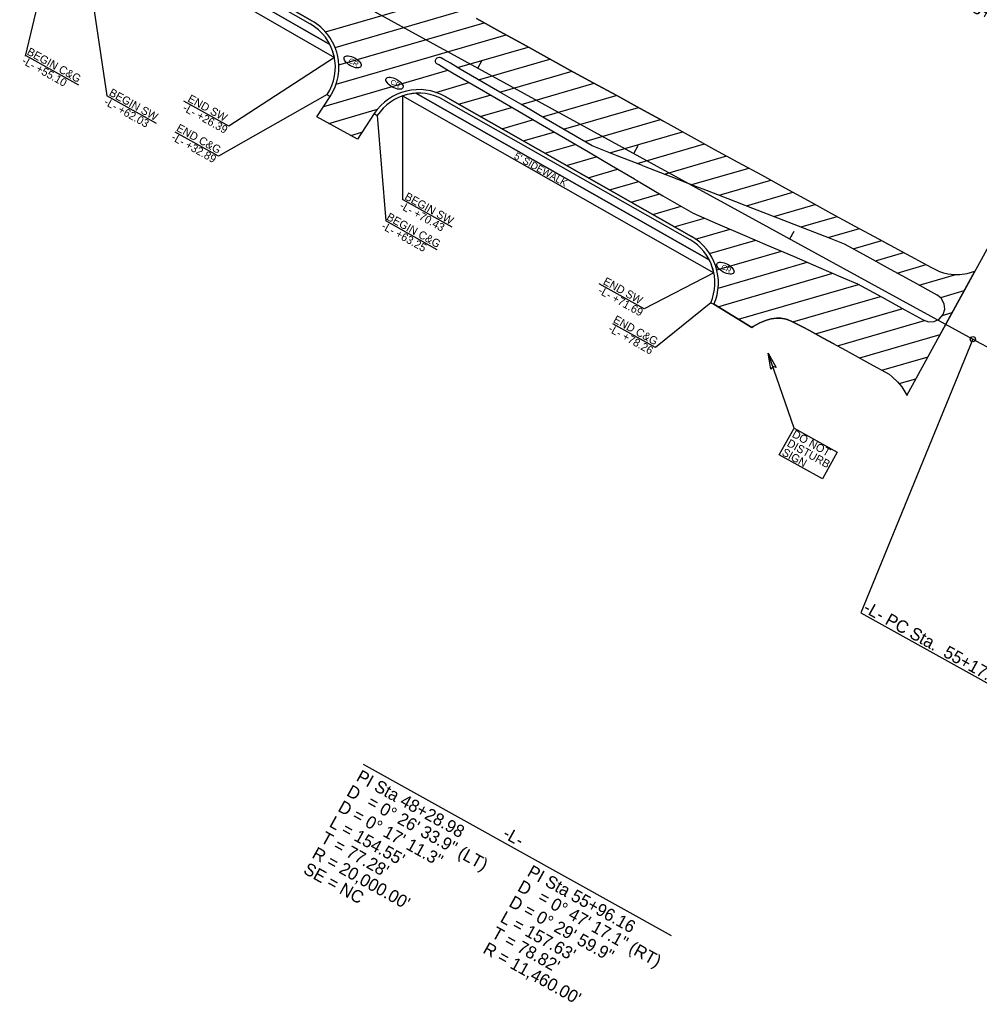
# Model space of a CAD drawing. Extents: x 1762196 to 1766326, y 709922 to 713142.
# Drawn here: x 1765252 to 1765792, y 709922 to 710474 of the extents above; entities that cross this region are included whole.
import ezdxf

# ---------------------------------------------------------------- set-up
doc = ezdxf.new("R2010")
doc.units = 0
for name, color, linetype in [('Old_Level_40', 7, 'Continuous'), ('Pattern 1', 7, 'Continuous'), ('Pattern 2', 7, 'Continuous'), ('Pattern 5', 7, 'Continuous'), ('Prop Conc 2ft 6in Curb and Gutter', 7, 'Continuous'), ('Prop Dimension', 7, 'Continuous'), ('Prop EOT', 7, 'Continuous'), ('Prop Horizontal Alignment', 7, 'Continuous'), ('Prop Horizontal Alignment Curve and Spiral Data', 7, 'Continuous'), ('Prop Horizontal Alignment Station Label', 7, 'Continuous'), ('Prop Horizontal Alignment Tick Large', 7, 'Continuous'), ('Prop Horizontal Alignment Tick Small', 7, 'Continuous'), ('Prop Terminator CELL', 7, 'Continuous')]:
    doc.layers.add(name, color=color, linetype=linetype)

msp = doc.modelspace()

# ---------------------------------------------------------------- linework, layer by layer
at = {"layer": 'Old_Level_40'}
for p, q in [((1765416.65, 710473.61), (1765368.58, 710501.28)), ((1765424.25, 710467.47), (1765488.61, 710486.17)), ((1765429.7, 710458.64), (1765501.05, 710479.37)), ((1765431.8, 710448.84), (1765513.45, 710472.56)), ((1765430.27, 710437.98), (1765525.81, 710465.73)), ((1765498.56, 710447.4), (1765538.19, 710458.92)), ((1765510.39, 710440.43), (1765550.48, 710452.07)), ((1765423.27, 710425.53), (1765493.1, 710445.82)), ((1765522.37, 710433.49), (1765562.97, 710445.29)), ((1765486.24, 710433.41), (1765505.02, 710438.87)), ((1765534.31, 710426.55), (1765575.41, 710438.49)), ((1765419.41, 710419.67), (1765426.89, 710431.03)), ((1765630.05, 710352.35), (1765491.58, 710431.03)), ((1765499.13, 710426.74), (1765516.9, 710431.9)), ((1765546.22, 710419.59), (1765587.81, 710431.68)), ((1765426.18, 710415.96), (1765453.51, 710423.9)), ((1765511.26, 710419.85), (1765528.83, 710424.96)), ((1765558.15, 710412.65), (1765600.28, 710424.89)), ((1765442.29, 710407.14), (1765419.41, 710419.67)), ((1765451.7, 710421.44), (1765442.29, 710407.14)), ((1765523.38, 710412.96), (1765540.76, 710418.01)), ((1765570.08, 710405.7), (1765612.64, 710418.06)), ((1765438.6, 710409.16), (1765444.8, 710410.96)), ((1765535.51, 710406.07), (1765552.67, 710411.06)), ((1765584.21, 710399.39), (1765625.03, 710411.25)), ((1765547.63, 710399.18), (1765564.58, 710404.1)), ((1765599.58, 710393.44), (1765637.41, 710404.43)), ((1765559.76, 710392.29), (1765576.51, 710397.16)), ((1765614.9, 710387.48), (1765649.86, 710397.64)), ((1765571.89, 710385.4), (1765588.44, 710390.21)), ((1765630.28, 710381.53), (1765662.32, 710390.84)), ((1765584.01, 710378.51), (1765600.38, 710383.26)), ((1765645.59, 710375.57), (1765674.68, 710384.02)), ((1765596.14, 710371.62), (1765612.3, 710376.31)), ((1765660.93, 710369.61), (1765687.11, 710377.22)), ((1765608.26, 710364.73), (1765624.22, 710369.36)), ((1765676.32, 710363.67), (1765699.64, 710370.44)), ((1765620.39, 710357.83), (1765637.31, 710362.75)), ((1765691.66, 710357.71), (1765712.03, 710363.63)), ((1765691.66, 710357.71), (1765712.03, 710363.63)), ((1765707, 710351.75), (1765724.53, 710356.85)), ((1765707, 710351.75), (1765724.53, 710356.85)), ((1765632.36, 710350.9), (1765651.74, 710356.53)), ((1765640.27, 710342.78), (1765666.21, 710350.32)), ((1765721.05, 710345.42), (1765737.02, 710350.06)), ((1765721.05, 710345.42), (1765737.02, 710350.06)), ((1765644.32, 710333.55), (1765680.66, 710344.1)), ((1765733.46, 710338.61), (1765749.51, 710343.28)), ((1765733.46, 710338.61), (1765749.51, 710343.28)), ((1765645.07, 710323.35), (1765695.11, 710337.89)), ((1765645.07, 710323.35), (1765695.11, 710337.89)), ((1765745.78, 710331.83), (1765762.03, 710336.55)), ((1765644.94, 710312.9), (1765709.55, 710331.67)), ((1765644.94, 710312.9), (1765709.55, 710331.67)), ((1765758.16, 710325.01), (1765778.66, 710330.96)), ((1765656.47, 710305.83), (1765723.91, 710325.43)), ((1765656.47, 710305.83), (1765723.91, 710325.43)), ((1765687.14, 710304.33), (1765736.43, 710318.65)), ((1765687.14, 710304.33), (1765736.43, 710318.65)), ((1765770.31, 710318.12), (1765783.43, 710321.94)), ((1765664.01, 710301.21), (1765642.7, 710314.27)), ((1765699.71, 710297.61), (1765747.05, 710311.37)), ((1765699.84, 710297.61), (1765748.82, 710311.84)), ((1765699.84, 710297.61), (1765748.82, 710311.84)), ((1765770.99, 710307.91), (1765776.65, 710309.55)), ((1765712.2, 710290.83), (1765761.14, 710305.05)), ((1765724.79, 710284.07), (1765769.86, 710297.17)), ((1765737.02, 710277.21), (1765763.08, 710284.78)), ((1765746.79, 710269.64), (1765756.3, 710272.4))]:
    msp.add_line(p, q, dxfattribs=at)
for points in [[(1765509.19, 710474.92), (1765522.3, 710467.65), (1765535.46, 710460.45), (1765548.54, 710453.13), (1765561.72, 710445.97), (1765574.88, 710438.78), (1765588.03, 710431.56), (1765601.2, 710424.38), (1765614.33, 710417.13)], [(1765614.33, 710417.13), (1765616.73, 710415.82), (1765629.87, 710408.59), (1765643, 710401.35), (1765656.19, 710394.21), (1765669.35, 710386.97), (1765682.47, 710379.7), (1765695.7, 710372.63), (1765708.82, 710365.37), (1765722, 710358.23), (1765735.18, 710351.06), (1765740.73, 710348.05)], [(1765710.03, 710292.01), (1765704.05, 710295.25), (1765696.38, 710299.53), (1765692.83, 710301.37), (1765685.83, 710305.02), (1765683.33, 710305.94), (1765680.35, 710306.48), (1765677.96, 710306.5), (1765674.95, 710306.08), (1765672.26, 710305.31), (1765668.48, 710303.83), (1765664.77, 710301.74), (1765664.01, 710301.21)]]:
    msp.add_lwpolyline(points, dxfattribs=at)
for centre, start, end in [((1765401.83, 710447.53), 326.6444, 60.3918), ((1765476.76, 710404.95), 60.3918, 146.6444), ((1765615.21, 710326.29), 336.3971, 60.3494)]:
    msp.add_arc(centre, 30, start, end, dxfattribs=at)
at = {"layer": 'Pattern 1'}
for p, q in [((1765362.98, 710491.24), (1765429.28, 710453.08)), ((1765467.63, 710431.42), (1765642.63, 710331.97)), ((1765640.07, 710339.18), (1765475.14, 710432.9))]:
    msp.add_line(p, q, dxfattribs=at)
msp.add_lwpolyline([(1765426.75, 710460.3), (1765365.41, 710495.6), (1765365.38, 710495.63)], dxfattribs=at)
for centre, start, end in [((1765401.83, 710447.53), 11.4296, 27.1395), ((1765476.76, 710404.95), 93.327, 109.0374), ((1765615.21, 710326.29), 11.7149, 27.4135)]:
    msp.add_arc(centre, 28, start, end, dxfattribs=at)
at = {"layer": 'Pattern 2'}
for p, q in [((1765365.34, 710495.65), (1765426.75, 710460.3)), ((1765362.85, 710491.31), (1765429.28, 710453.08)), ((1765467.63, 710431.42), (1765642.63, 710331.97)), ((1765475.14, 710432.9), (1765640.07, 710339.18))]:
    msp.add_line(p, q, dxfattribs=at)
for centre, start, end in [((1765401.83, 710447.53), 11.4296, 27.1395), ((1765476.76, 710404.95), 93.327, 109.0374), ((1765615.21, 710326.29), 11.7149, 27.4135)]:
    msp.add_arc(centre, 28, start, end, dxfattribs=at)
at = {"layer": 'Pattern 5'}
for centre in [(1765439.54, 710450.57), (1765463.08, 710438.57), (1765649.13, 710334.56)]:
    msp.add_ellipse(centre, major_axis=(4.7, -2.63), ratio=0.462467, dxfattribs=at)
at = {"layer": 'Prop Conc 2ft 6in Curb and Gutter'}
for p, q in [((1765367.58, 710499.55), (1765415.65, 710471.88)), ((1765425.22, 710432.13), (1765426.89, 710431.03)), ((1765490.6, 710429.29), (1765629.06, 710350.61)), ((1765451.7, 710421.44), (1765453.37, 710420.34)), ((1765640.87, 710315.08), (1765642.7, 710314.27))]:
    msp.add_line(p, q, dxfattribs=at)
for centre, start, end in [((1765401.83, 710447.53), 326.6444, 60.3918), ((1765476.76, 710404.95), 60.3918, 146.6444), ((1765615.21, 710326.29), 336.3971, 60.3494)]:
    msp.add_arc(centre, 28, start, end, dxfattribs=at)
at = {"layer": 'Prop Dimension'}
for p, q in [((1765286.09, 710533.81), (1765301.32, 710431.55)), ((1765271.97, 710522.45), (1765255.34, 710453.77)), ((1765285.5, 710437.52), (1765255.98, 710453.96)), ((1765429.28, 710453.08), (1765369.91, 710414.35)), ((1765329.31, 710415.98), (1765301.32, 710431.55)), ((1765425.22, 710432.13), (1765364.05, 710397.58)), ((1765467.63, 710431.42), (1765467.51, 710373.14)), ((1765369.91, 710414.35), (1765344.58, 710428.44)), ((1765453.37, 710420.34), (1765458.14, 710361.09)), ((1765364.05, 710397.58), (1765339.77, 710411.1)), ((1765495.5, 710357.58), (1765467.51, 710373.14)), ((1765487.13, 710344.95), (1765458.14, 710361.09)), ((1765642.63, 710331.97), (1765603.48, 710311.64)), ((1765603.48, 710311.64), (1765578.15, 710325.72)), ((1765640.87, 710315.08), (1765609.75, 710289.92)), ((1765609.75, 710289.92), (1765585.8, 710303.26)), ((1765687.74, 710244.49), (1765673.21, 710286.72))]:
    msp.add_line(p, q, dxfattribs=at)
msp.add_lwpolyline([(1765687.74, 710244.49), (1765711.96, 710231), (1765703.65, 710216.07), (1765679.43, 710229.56)], close=True, dxfattribs=at)
at = {"layer": 'Prop EOT'}
for p, q in [((1765368.58, 710501.28), (1765416.65, 710473.61)), ((1765419.41, 710419.67), (1765426.89, 710431.03)), ((1765491.58, 710431.03), (1765630.05, 710352.35)), ((1765442.29, 710407.14), (1765419.41, 710419.67)), ((1765451.7, 710421.44), (1765442.29, 710407.14)), ((1765751.1, 710262.91), (1765789.38, 710332.79)), ((1765642.7, 710314.27), (1765643.62, 710313.87)), ((1765642.7, 710314.27), (1765664.01, 710301.21))]:
    msp.add_line(p, q, dxfattribs=at)
for points in [[(1765614.33, 710417.13), (1765601.2, 710424.38), (1765588.03, 710431.56), (1765574.88, 710438.78), (1765561.72, 710445.97), (1765548.54, 710453.13), (1765535.46, 710460.45), (1765522.3, 710467.65), (1765509.19, 710474.92)], [(1765598.03, 710384.61), (1765585.08, 710392.17), (1765572.11, 710399.72), (1765559.15, 710407.27), (1765546.22, 710414.83), (1765533.26, 710422.38), (1765520.29, 710429.91), (1765507.36, 710437.5), (1765497.97, 710442.98), (1765492.52, 710446.16), (1765488.03, 710448.8), (1765486.91, 710449.47), (1765486.37, 710450.09), (1765486.15, 710450.79), (1765486.13, 710451.51), (1765486.46, 710452.27), (1765487.02, 710452.8), (1765487.68, 710453.08), (1765488.36, 710453.13), (1765488.98, 710452.95)], [(1765602.48, 710392.32), (1765588.31, 710397.79), (1765574.18, 710403.31), (1765561.22, 710410.86), (1765548.31, 710418.37), (1765535.36, 710425.94), (1765522.38, 710433.45), (1765509.42, 710440.99), (1765502.29, 710445.19), (1765500.06, 710446.5), (1765494.64, 710449.74), (1765490.9, 710451.84), (1765488.98, 710452.95)], [(1765614.33, 710417.13), (1765616.73, 710415.82), (1765629.87, 710408.59), (1765643, 710401.35), (1765656.19, 710394.21), (1765669.35, 710386.97), (1765682.47, 710379.7), (1765695.7, 710372.63), (1765708.82, 710365.37), (1765722, 710358.23), (1765735.18, 710351.06), (1765748.36, 710343.9), (1765765.08, 710334.91), (1765769.48, 710332.76), (1765771.8, 710331.93), (1765774.13, 710331.39), (1765777.98, 710330.96), (1765781.01, 710330.96), (1765785, 710331.51), (1765789.38, 710332.79)], [(1765602.48, 710392.32), (1765604.38, 710391.54), (1765618.38, 710386.13), (1765632.37, 710380.73), (1765636.44, 710379.13), (1765650.42, 710373.68), (1765664.45, 710368.25), (1765678.45, 710362.85), (1765693.5, 710356.99)], [(1765598.03, 710384.61), (1765600.94, 710382.94), (1765614.03, 710375.3), (1765627.13, 710367.66), (1765630.98, 710365.49), (1765644.75, 710359.53), (1765658.81, 710353.5), (1765672.61, 710347.58), (1765687.73, 710341.05)], [(1765693.5, 710356.99), (1765707.49, 710351.56), (1765715.88, 710348.25), (1765728.62, 710341.28), (1765741.76, 710334.04), (1765754.89, 710326.81), (1765768.03, 710319.56)], [(1765687.73, 710341.05), (1765701.52, 710335.14), (1765715.29, 710329.19), (1765723.33, 710325.74), (1765736.89, 710318.4), (1765750.03, 710311.17), (1765760.27, 710305.52), (1765763.43, 710304.45), (1765766.59, 710304.62), (1765769.32, 710305.95), (1765771.57, 710308.59), (1765772.5, 710311.5), (1765772.24, 710314.5), (1765770.55, 710317.67), (1765768.03, 710319.56)], [(1765664.01, 710301.21), (1765664.77, 710301.74), (1765668.48, 710303.83), (1765672.26, 710305.31), (1765674.95, 710306.08), (1765677.96, 710306.5), (1765680.35, 710306.48), (1765683.33, 710305.94), (1765685.83, 710305.02), (1765692.83, 710301.37), (1765696.38, 710299.53), (1765704.05, 710295.25), (1765717.03, 710288.21), (1765730.21, 710281.03), (1765741.17, 710274.88), (1765742.95, 710273.54), (1765745.94, 710270.68), (1765748.33, 710267.76), (1765751.18, 710263.06)]]:
    msp.add_lwpolyline(points, dxfattribs=at)
for centre, start, end in [((1765401.83, 710447.53), 326.6444, 60.3918), ((1765476.76, 710404.95), 60.3918, 146.6444), ((1765615.21, 710326.29), 336.3971, 60.3494)]:
    msp.add_arc(centre, 30, start, end, dxfattribs=at)
at = {"layer": 'Prop Horizontal Alignment'}
msp.add_line((1765252.32, 710588.23), (1765788.26, 710294.65), dxfattribs=at)
msp.add_arc((1760282.51, 700243.86), 11460, 60.49827, 61.286353, dxfattribs=at)
at = {"layer": 'Prop Horizontal Alignment Curve and Spiral Data'}
msp.add_line((1765445.49, 710055.65), (1765618.61, 709959.24), dxfattribs=at)
at = {"layer": 'Prop Horizontal Alignment Station Label'}
for p, q in [((1765859.08, 710460.02), (1765773.05, 710302.98)), ((1765788.26, 710294.65), (1765725.38, 710140.71)), ((1765725.38, 710140.71), (1765816.18, 710090.15))]:
    msp.add_line(p, q, dxfattribs=at)
msp.add_circle((1765788.26, 710294.65), 1.5, dxfattribs=at)
at = {"layer": 'Prop Horizontal Alignment Tick Large'}
for q in [(1765776.89, 710310), (1765776.89, 710310), (1765769.2, 710295.96), (1765769.2, 710295.96)]:
    msp.add_line((1765773.05, 710302.98), q, dxfattribs=at)
at = {"layer": 'Prop Horizontal Alignment Tick Small'}
for p, q in [((1765509.94, 710447.11), (1765512.34, 710451.49)), ((1765509.94, 710447.11), (1765512.34, 710451.49)), ((1765597.64, 710399.07), (1765600.04, 710403.45)), ((1765597.64, 710399.07), (1765600.04, 710403.45)), ((1765685.34, 710351.02), (1765687.75, 710355.41)), ((1765685.35, 710351.02), (1765687.75, 710355.41))]:
    msp.add_line(p, q, dxfattribs=at)
at = {"layer": 'Prop Terminator CELL'}
msp.add_lwpolyline([(1765674.67, 710277.7), (1765673.21, 710286.72), (1765677.67, 710278.68), (1765675.78, 710279.25)], close=True, dxfattribs=at)

# ---------------------------------------------------------------- texts
at = {"layer": 'Pattern 5'}
for p in [(1765436.88, 710450.43), (1765460.41, 710438.44), (1765646.47, 710334.43)]:
    msp.add_text('CR', height=2.88, rotation=330.7692, dxfattribs=at).set_placement(p)
at = {"layer": 'Prop Dimension'}
for s, height, rotation, p in [('BEGIN C&G', 4.5, 330.8875, (1765255.99, 710454.95)), ('-L- +55.10', 4.5, 330.8875, (1765253.15, 710449.84)), ('BEGIN SW', 4.5, 330.9251, (1765302.16, 710431.92)), ('-L- +62.03', 4.5, 330.9251, (1765299.32, 710426.8)), ('END SW', 4.5, 330.9251, (1765346.4, 710428.51)), ('-L- +26.39', 4.5, 330.9251, (1765343.55, 710423.4)), ('END C&G', 4.5, 330.8875, (1765340.01, 710412.03)), ('-L- +32.89', 4.5, 330.8875, (1765337.16, 710406.91)), ("5' SIDEWALK", 4, 330.8354, (1765529.92, 710396.46)), ('BEGIN SW', 4.5, 330.9251, (1765468.35, 710373.51)), ('-L- +70.43', 4.5, 330.9251, (1765465.51, 710368.4)), ('BEGIN C&G', 4.5, 330.8875, (1765458.16, 710362.04)), ('-L- +63.25', 4.5, 330.8875, (1765455.32, 710356.93)), ('END SW', 4.5, 330.9251, (1765579.97, 710325.8)), ('-L- +71.69', 4.5, 330.9251, (1765577.13, 710320.68)), ('END C&G', 4.5, 330.8875, (1765585.67, 710304.35)), ('-L- +78.26', 4.5, 330.8875, (1765582.82, 710299.24)), ('DO NOT ', 4.5, 330.8875, (1765686.2, 710239.89)), ('DISTURB', 4.5, 330.8875, (1765683.35, 710234.78)), ('SIGN', 4.5, 330.8875, (1765680.51, 710229.67))]:
    msp.add_text(s, height=height, rotation=rotation, dxfattribs=at).set_placement(p)
at = {"layer": 'Prop Horizontal Alignment Curve and Spiral Data'}
for s, p in [('PI Sta 48+28.98', (1765441.04, 710046.68)), ('D', (1765435.59, 710038.27)), ('= 0%%d 26\' 33.9" (LT)', (1765446.96, 710032.28)), ('D = 0%%d 17\' 11.3"', (1765430.72, 710029.53)), ("L = 154.55'", (1765425.86, 710020.8)), ("T = 77.28'", (1765420.99, 710012.06)), ('-L-', (1765523.39, 710014.67)), ("R = 20,000.00'", (1765416.13, 710003.32)), ('SE = NC', (1765411.26, 709994.59)), ('PI Sta 55+96.16', (1765537.16, 709993.16)), ('D', (1765531.7, 709984.75)), ('D = 0%%d 29\' 59.9"', (1765526.84, 709976.01)), ('= 0%%d 47\' 17.1" (RT)', (1765543.07, 709978.75)), ("L = 157.63'", (1765521.97, 709967.27)), ("T = 78.82'", (1765517.11, 709958.54)), ("R = 11,460.00'", (1765512.24, 709949.8))]:
    msp.add_text(s, height=7, rotation=330.8875, dxfattribs=at).set_placement(p)
at = {"layer": 'Prop Horizontal Alignment Station Label'}
for s, p in [('-L- POT Sta.  55+00.00', (1765732.31, 710509.57)), ('-L- PC Sta.  55+17.35', (1765726.12, 710141.58))]:
    msp.add_text(s, height=7, rotation=330.8875, dxfattribs=at).set_placement(p)

doc.saveas('drawing.dxf')
